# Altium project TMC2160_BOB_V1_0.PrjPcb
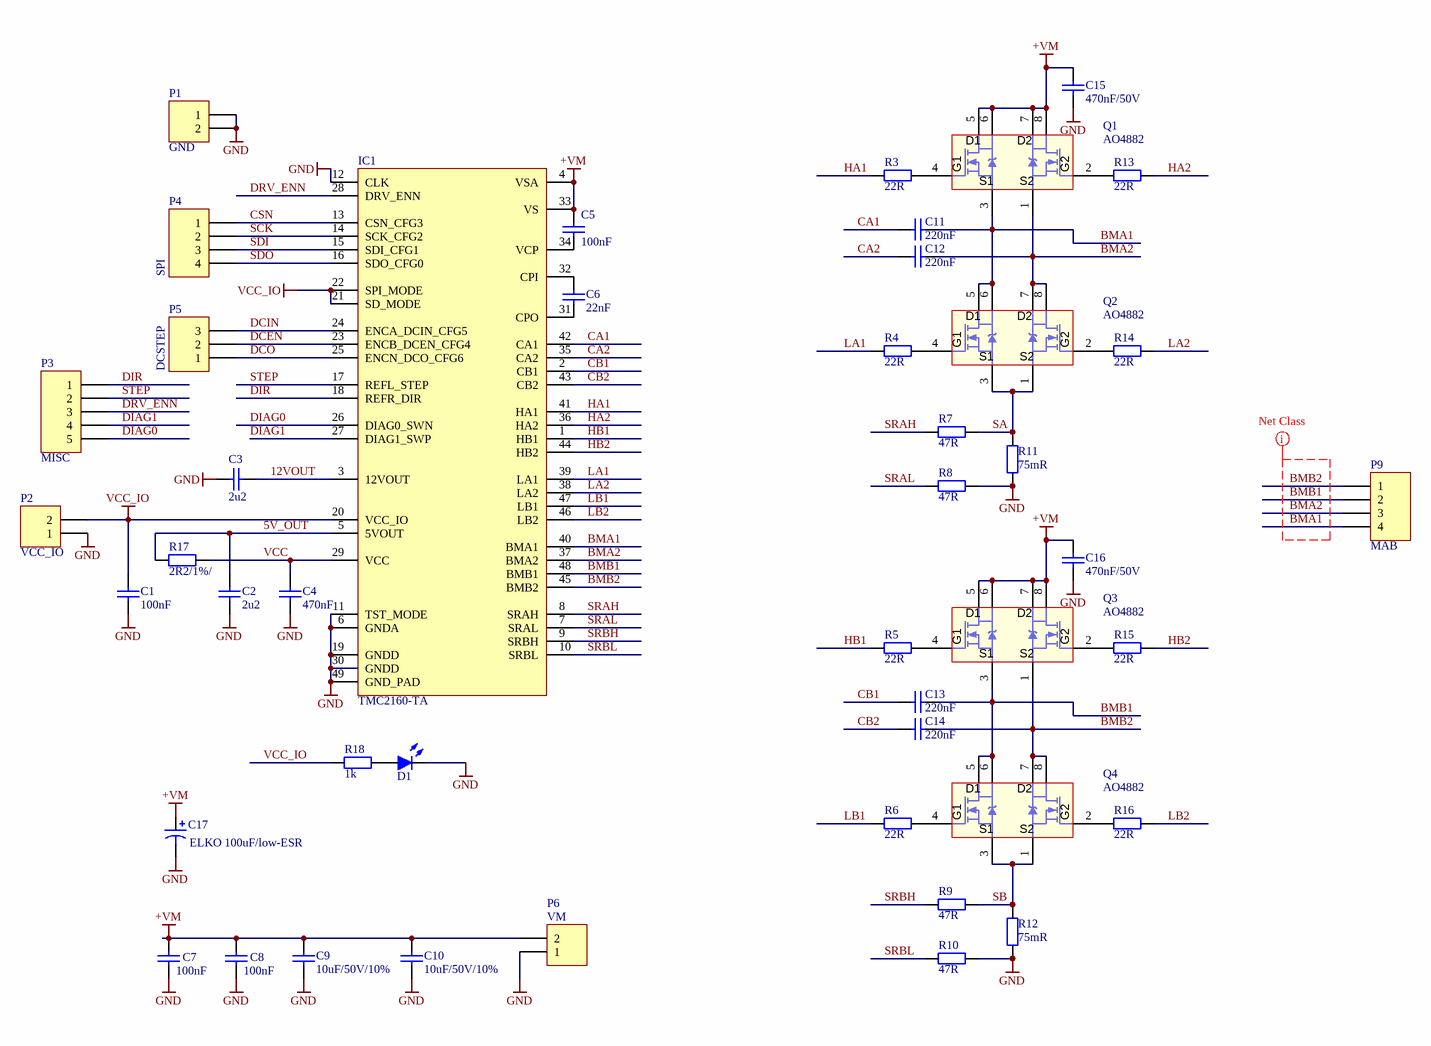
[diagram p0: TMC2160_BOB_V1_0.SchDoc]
BoardName: TMC2160_BOB; BoardVersion: 1.0
2 sheets, 46 parts. Net scope: global (net labels, ports and power ports of the same name join across sheets).
Board file: TMC2160_BOB_V1_0.PcbDoc
Sheets:
  TMC2160_BOB_V1_0.SchDoc
  ChangeLog.SchDoc

## Sheet TMC2160_BOB_V1_0.SchDoc
size A3; DocumentNumber: 1; SheetNumber: 1; SheetTotal: 2

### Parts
C1  100nF  [C0603]
C2  2u2  [C0603]
C3  2u2  [C0603]
C4  470nF  [C0603]
C5  100nF  [C0603]
C6  22nF  [C0603]
C7  100nF  [C0603]
C8  100nF  [C0603]
C9  10uF/50V/10%  [C1206]
C10  10uF/50V/10%  [C1206]
C11  220nF  [C0603]
C12  220nF  [C0603]
C13  220nF  [C0603]
C14  220nF  [C0603]
C15  470nF/50V  [C0603]
C16  470nF/50V  [C0603]
C17  value ELKO 100uF/low-ESR  [EXT_POL_CAP]  (hidden comment: Cap Pol1)
D1  LED, Blue, SMD, 20mA, 2.8V, 465 nm  [LED_0603]  (value not drawn)
IC1  TMC2160-TA  [TMC5160_TSQFP50P900X900X120_HS-49L]
P1  GND  [2_PIN_THT]
P2  VCC_IO  [2_PIN_THT]
P3  MISC  [5_PIN_THT]
P4  SPI  [4_PIN_THT]
P5  DCSTEP  [3_PIN_THT]
P6  VM  [2_PIN_THT]
P9  MAB  [4_PIN_THT_1mm_hole]
Q1  AO4882  [SOP127P600X170-8L]
Q2  AO4882  [SOP127P600X170-8L]
Q3  AO4882  [SOP127P600X170-8L]
Q4  AO4882  [SOP127P600X170-8L]
R3  Resistance: 22R  [R0603]  (hidden comment: 22R / 100mW / 1%)
R4  Resistance: 22R  [R0603]  (hidden comment: 22R / 100mW / 1%)
R5  Resistance: 22R  [R0603]  (hidden comment: 22R / 100mW / 1%)
R6  Resistance: 22R  [R0603]  (hidden comment: 22R / 100mW / 1%)
R7  Resistance: 47R  [R0603]  (hidden comment: 47R /  / 1%)
R8  Resistance: 47R  [R0603]  (hidden comment: 47R /  / 1%)
R9  Resistance: 47R  [R0603]  (hidden comment: 47R /  / 1%)
R10  Resistance: 47R  [R0603]  (hidden comment: 47R /  / 1%)
R11  75mR  [R1206]
R12  75mR  [R1206]
R13  Resistance: 22R  [R0603]  (hidden comment: 22R / 100mW / 1%)
R14  Resistance: 22R  [R0603]  (hidden comment: 22R / 100mW / 1%)
R15  Resistance: 22R  [R0603]  (hidden comment: 22R / 100mW / 1%)
R16  Resistance: 22R  [R0603]  (hidden comment: 22R / 100mW / 1%)
R17  2R2/1%/  [R0603]
R18  1k  [R0603]

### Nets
+VM: C5.1 C7.1 C8.1 C9.2 C10.2 C15.1 C16.1 C17.1 IC1.4(VSA) IC1.33(VS) P6.2 Q1.5(D1) Q1.6(D1) Q1.7(D2) Q1.8(D2) Q3.5(D1) Q3.6(D1) Q3.7(D2) Q3.8(D2)
GND: C1.2 C2.2 C3.1 C4.2 C7.2 C8.2 C9.1 C10.1 C15.2 C16.2 C17.2 D1.2(K) IC1.6(GNDA) IC1.11(TST_MODE) IC1.12(CLK) IC1.19(GNDD) IC1.30(GNDD) IC1.49(GND_PAD) P1.1 P1.2 P2.1 P6.1 R8.1 R10.1 R11.2 R12.2
VCC_IO: C1.1 IC1.20(VCC_IO) IC1.21(SD_MODE) IC1.22(SPI_MODE) P2.2 R18.1
5V_OUT: C2.1 IC1.5(5VOUT) R17.1
12VOUT: C3.2 IC1.3(12VOUT)
BMA1: C11.2 IC1.40(BMA1) P9.4 Q1.3(S1) Q2.5(D1) Q2.6(D1)
BMA2: C12.2 IC1.37(BMA2) P9.3 Q1.1(S2) Q2.7(D2) Q2.8(D2)
BMB1: C13.2 IC1.48(BMB1) P9.2 Q3.3(S1) Q4.5(D1) Q4.6(D1)
BMB2: C14.2 IC1.45(BMB2) P9.1 Q3.1(S2) Q4.7(D2) Q4.8(D2)
CA1: C11.1 IC1.42(CA1)
CA2: C12.1 IC1.35(CA2)
CB1: C13.1 IC1.2(CB1)
CB2: C14.1 IC1.43(CB2)
CSN: IC1.13(CSN_CFG3) P4.1
DCEN: IC1.23(ENCB_DCEN_CFG4) P5.2
DCIN: IC1.24(ENCA_DCIN_CFG5) P5.3
DCO: IC1.25(ENCN_DCO_CFG6) P5.1
DIAG0: IC1.26(DIAG0_SWN) P3.5
DIAG1: IC1.27(DIAG1_SWP) P3.4
DIR: IC1.18(REFR_DIR) P3.1
DRV_ENN: IC1.28(DRV_ENN) P3.3
HA1: IC1.41(HA1) R3.2
HA2: IC1.36(HA2) R13.1
HB1: IC1.1(HB1) R5.2
HB2: IC1.44(HB2) R15.1
LA1: IC1.39(LA1) R4.2
LA2: IC1.38(LA2) R14.1
LB1: IC1.47(LB1) R6.2
LB2: IC1.46(LB2) R16.1
SA: Q2.1(S2) Q2.3(S1) R7.1 R11.1
SB: Q4.1(S2) Q4.3(S1) R9.1 R12.1
SCK: IC1.14(SCK_CFG2) P4.2
SDI: IC1.15(SDI_CFG1) P4.3
SDO: IC1.16(SDO_CFG0) P4.4
SRAH: IC1.8(SRAH) R7.2
SRAL: IC1.7(SRAL) R8.2
SRBH: IC1.9(SRBH) R9.2
SRBL: IC1.10(SRBL) R10.2
STEP: IC1.17(REFL_STEP) P3.2
VCC: C4.1 IC1.29(VCC) R17.2
NetC5_2: C5.2 IC1.34(VCP)
NetC6_1: C6.1 IC1.31(CPO)
NetC6_2: C6.2 IC1.32(CPI)
NetD1_1: D1.1(A) R18.2
NetQ1_2: Q1.2(G2) R13.2
NetQ1_4: Q1.4(G1) R3.1
NetQ2_2: Q2.2(G2) R14.2
NetQ2_4: Q2.4(G1) R4.1
NetQ3_2: Q3.2(G2) R15.2
NetQ3_4: Q3.4(G1) R5.1
NetQ4_2: Q4.2(G2) R16.2
NetQ4_4: Q4.4(G1) R6.1

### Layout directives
net class MotorPowerOut: BMA1, BMA2, BMB1, BMB2

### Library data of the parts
C1 C5 = Capacitor: Ceramic capacitor; MPN: MC0603F104M500CT; Type: MLCC; Voltage rating: 50V; ComponentLinknDescription: Datasheet; MF: Multicomp; Precision: 20%
C2 C3 = 2.2 µF, 25 V, ± 10%, X5R, GRM Series: SMD Multilayer Ceramic Capacitor, 0603 [1608 Metric], 2.2 µF, 25 V, ± 10%, X5R, GRM Series; MPN: GRM188R61E225KA12D; Type: MLCC; Voltage rating: 50V; ComponentLinknDescription: Datasheet; MF: MURATA
C4 = Capacitor: Ceramic capacitor; MPN: MC0603X474K160CT; Type: MLCC; Voltage rating: 16V; ComponentLinknDescription: Datasheet; MF: Multicomp; Precision: 10%
C6 = Capacitor: Ceramic capacitor; MPN: MC0603B223K500CT; Type: MLCC; Voltage rating: 50V; ComponentLinknDescription: Datasheet; MF: Multicomp; Precision: 20%
C7 C8 = Capacitor: Ceramic capacitor; Manufacturer: Multicomp; MPN: MC0603F104M500CT; Type: MLCC; Voltage rating: 50V; ComponentLinknDescription: Datasheet; Precision: 20%
C9 C10 = 10 µF, 50 V, ± 20%, X5R, GRM Series: SMD Multilayer Ceramic Capacitor, 1206 [3216 Metric], 10 µF, 50 V, ± 20%, X5R, GRM Series; MPN: GRM31CR61H106MA12L; Type: MLCC; VoltageRating: 50V; ComponentLinknDescription: Datasheet; MF: MURATA; Capacitance: 10uF; Precision: 10%
C11-C14 = 0.22 µF, 50 V, ± 10%, X7R: SMD Multilayer Ceramic Capacitor, 0603 [1608 Metric], 0.22 µF, 50 V, ± 10%, X7R, GCM Series; MPN: GCM188R71H224KA64D; Type: MLCC; Voltage rating: 50V; ComponentLinknDescription: Datasheet; MF: MURATA
C15 = 0.47 µF, 50 V, ± 10%, X7R, C Series: SMD Multilayer Ceramic Capacitor, 0603 [1608 Metric], 0.47 µF, 50 V, ± 10%, X7R, C Series; MPN: C1608X7R1H474K080AC; Type: MLCC; VoltageRating: 50V; ComponentLinknDescription: Datasheet; MF: TDK; Capacitance: 470nF
C16 = 0.47 µF, 50 V, ± 10%, X7R, C Series: SMD Multilayer Ceramic Capacitor, 0603 [1608 Metric], 0.47 µF, 50 V, ± 10%, X7R, C Series; MPN: C1608X7R1H474K080AC; Type: MLCC; ComponentLinknDescription: Datasheet; MF: TDK; Capacitance: 470nF; VoltageRating: 50V
C17 = Cap Pol1: Polarized Capacitor (Radial)
D1 = LED, Blue, SMD, 20mA, 2.8V, 465 nm: MPN: LTST-C191TBKT-5A; MF: Lite-On
IC1 = TMC2160-TA: Manufacturer: TRINAMIC; Geometry.Height: 1,2mm
P1 P2 P6 = Header 2: Header, 2-Pin; Fitted: Not fitted
P3 = Header 5: Header, 5-Pin; Fitted: Not fitted
P4 = Header 4: Header, 4-Pin; Fitted: Not fitted
P5 = Header 3: Header, 3-Pin; Fitted: Not fitted
P9 = Wire-To-Board Connector, 2.5 mm, 4 Contacts, Header, EH Series, Through Hole, 1 Rows: MPN: B4B-EH-A; MF: JST (JAPAN SOLDERLESS TERMINALS); Fitted: Not fitted
Q1-Q4 = AO4882 MOSFET 2N-CH 40V 8A 8SOIC: Mosfet Array 2 N-Channel (Dual) 40V 8A 2W Surface Mount 8-SOIC; MF: Alpha & Omega Semiconductor Inc.
R3-R6 R13-R16 = 22 ohm, 50 V, 0603 [1608 Metric], 100 mW, ± 1%, MCWR Series: SMD Chip Resistor, Thick Film, 22 ohm, 50 V, 0603 [1608 Metric], 100 mW, ± 1%, MCWR Series; MPN: MCWR06X22R0FTLV; Temp coefficient: *ppm; MF: MULTICOMP
R7-R10 = 47 ohm, 75 V, 0603 [1608 Metric], 100 mW, ± 1%, MCSR 06 Series: SMD Chip Resistor, Ceramic, 47 ohm, 75 V, 0603 [1608 Metric], 100 mW, ± 1%, MCSR 06 Series; MPN: MCSR06X47R0FTL; Temp coefficient: *ppm; MF: MULTICOMP
R11 R12 = R_SENS, 0.075 ohm, 1206, 1W, ± 1%, ERJ Series: SMD Chip Resistor, Thick Film, Current Sense Resistors - SMD 1W 0.075ohm 1%; MPN: ERJ-8BWFR075V; VoltageRating: 50V; Temp coefficient: *ppm; MF: Panasonic Electronic Components
R17 = Resistor: MPN: MC0063W060312R2; Precision: 1%; Voltage rating: *V; Temp coefficient: *ppm; Power rating: *mW; ComponentLinknDescription: Datasheet; Resistance: 2R2; MF: Multicomp
R18 = 1 kohm, 50 V, 0603 [1608 Metric], 63 mW, ± 1%, MC Series: MPN: MC0063W060311K; VoltageRating: 50V; Temp coefficient: *ppm; PowerRating: 63mW; MF: MULTICOMP

## Sheet ChangeLog.SchDoc
size A4; DocumentNumber: 2; SheetNumber: 2; SheetTotal: 2
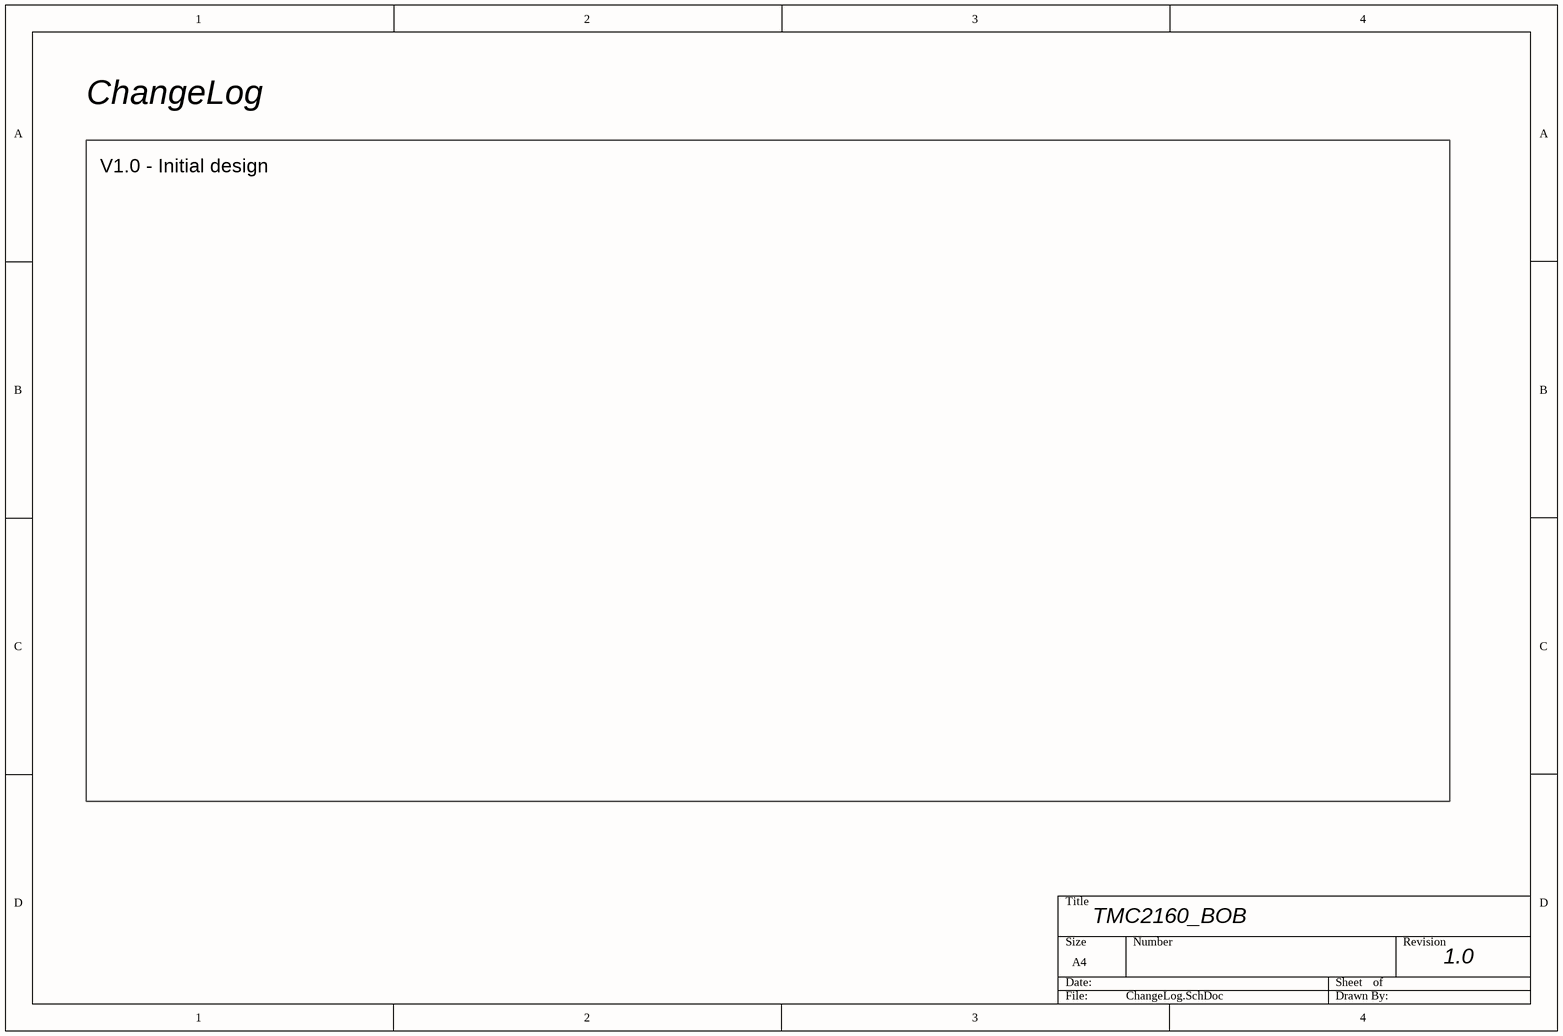
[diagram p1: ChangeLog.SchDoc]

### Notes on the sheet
- ChangeLog
- V1.0 - Initial design

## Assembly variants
TMC2160_RevA: not fitted C17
